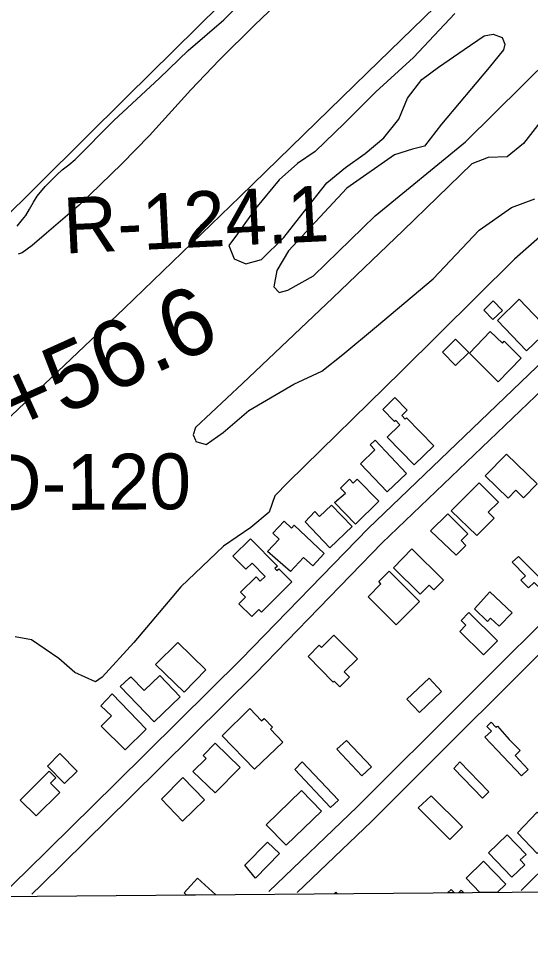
# Model space of a CAD drawing. Extents: x 3568792 to 3606828, y 529143 to 554785.
# Drawn here: x 3579710 to 3580470, y 534531 to 535909 of the extents above; entities that cross this region are included whole.
import ezdxf

# ---------------------------------------------------------------- set-up
doc = ezdxf.new("R2010")
doc.units = 0
for name, color, linetype in [('V-BLDG-OTLN', 7, 'Continuous'), ('V-DTCH-CNTR', 7, 'Continuous'), ('V-GRID-FRAM', 7, 'Continuous'), ('V-RIVR-RANG-IDEN', 7, 'Continuous'), ('V-ROAD-CNTR', 7, 'Continuous'), ('V-SITE-VEGE', 7, 'Continuous'), ('V-SURV-IDEN', 7, 'Continuous')]:
    doc.layers.add(name, color=color, linetype=linetype)

msp = doc.modelspace()

# ---------------------------------------------------------------- linework, layer by layer
at = {"layer": 'V-BLDG-OTLN'}
for p, q in [((3580374.8, 534631.4), (3580400.8, 534656.7)), ((3580400.8, 534656.7), (3580433.9, 534622.4)), ((3579955.9, 534609.4), (3579975.7, 534631.5)), ((3579975.7, 534631.5), (3580003, 534606.6)), ((3580395.5, 534609.9), (3580374.8, 534631.4)), ((3579959.4, 534606.2), (3579955.9, 534609.4)), ((3580178.9, 534608.1), (3580181.4, 534610.6)), ((3580181.4, 534610.6), (3580183.9, 534608.1)), ((3580347.4, 534609.5), (3580352.9, 534614.5)), ((3580357.8, 534609.6), (3580347.4, 534609.5)), ((3580352.9, 534614.5), (3580357.8, 534609.6)), ((3580363.6, 534609.6), (3580367.5, 534613.5)), ((3580371.3, 534609.7), (3580363.6, 534609.6)), ((3580367.5, 534613.5), (3580371.3, 534609.7)), ((3580421.2, 534610.1), (3580395.5, 534609.9)), ((3580433.9, 534622.4), (3580421.2, 534610.1)), ((3580003, 534606.6), (3579959.4, 534606.2)), ((3580183.9, 534608.1), (3580178.9, 534608.1))]:
    msp.add_line(p, q, dxfattribs=at)
for points in [[(3580421.6, 535460.7), (3580453.9, 535492.1), (3580497.3, 535446.5), (3580464.7, 535415.5)], [(3580401.2, 535476), (3580415.2, 535489.6), (3580428.8, 535475.4), (3580414.7, 535461.9)], [(3580379.7, 535411.8), (3580410.6, 535444.2), (3580429, 535426.9), (3580431.3, 535429.7), (3580456.7, 535404.5), (3580422.7, 535369.5)], [(3580339.6, 535413.5), (3580359.3, 535432.7), (3580378.7, 535412.7), (3580358.9, 535393.5)], [(3580257.7, 535286.8), (3580276.6, 535305.6), (3580270.3, 535311.9), (3580268.6, 535310.2), (3580251, 535328.1), (3580269.2, 535345.9), (3580287.4, 535327.3), (3580279.2, 535319.3), (3580284.4, 535314), (3580286.1, 535315.6), (3580326.7, 535274.2), (3580297.8, 535245.9)], [(3580217.9, 535247.4), (3580239.4, 535268.4), (3580232.5, 535275.7), (3580239.8, 535282.6), (3580286.5, 535233.2), (3580257.5, 535205.7)], [(3580403.4, 535229.4), (3580434.8, 535261.6), (3580480.4, 535217.4), (3580460.3, 535196.7), (3580448.6, 535208), (3580437.4, 535196.4)], [(3580179.4, 535190), (3580195.5, 535204), (3580188.2, 535211.4), (3580201.5, 535224.4), (3580207.1, 535218.7), (3580213.1, 535224.7), (3580245.3, 535191.7), (3580210.7, 535157.9)], [(3580352.8, 535177.5), (3580394.3, 535219.2), (3580423.1, 535190.5), (3580407.9, 535175.3), (3580416.6, 535166.6), (3580390.7, 535140.6)], [(3580135.7, 535161.1), (3580150, 535176.3), (3580156.9, 535169), (3580174.8, 535186.1), (3580205.5, 535154.1), (3580172.6, 535122.6)], [(3580079.9, 535117), (3580097.1, 535135.4), (3580087.7, 535144.2), (3580104.3, 535162), (3580115.3, 535151.7), (3580119.4, 535156.1), (3580164.2, 535114), (3580146.9, 535095.6), (3580133.3, 535108.3), (3580113.7, 535087.4)], [(3580321.8, 535147.7), (3580347.5, 535173.2), (3580377.3, 535143.2), (3580367.3, 535133.3), (3580374.7, 535125.9), (3580360.2, 535111.6)], [(3580028.3, 535110.1), (3580054.4, 535135.8), (3580094.5, 535095.2), (3580090.9, 535091.7), (3580093.7, 535088.8), (3580096.5, 535091.5), (3580116, 535071.7), (3580070.7, 535027), (3580066.9, 535030.9), (3580056.3, 535020.4), (3580037.4, 535039.4), (3580047.2, 535049.1), (3580039.9, 535056.5), (3580062.8, 535079.2), (3580069.1, 535072.9), (3580076.4, 535080), (3580057, 535099.8), (3580047.8, 535090.7)], [(3580267, 535092.7), (3580294, 535121), (3580341.1, 535074.3), (3580327, 535060.1), (3580319.8, 535067.2), (3580306.4, 535053.6)], [(3580452.6, 535109.5), (3580495.2, 535067.1), (3580487.7, 535059.5), (3580476.1, 535071.1), (3580467.7, 535062.8), (3580456.3, 535074.2), (3580463.1, 535081), (3580443.1, 535101)], [(3580229.3, 535049.8), (3580248.3, 535069.1), (3580245, 535072.4), (3580260.4, 535087.9), (3580305.4, 535042.8), (3580270.8, 535008.2)], [(3580410.2, 535057.2), (3580443.2, 535025.8), (3580424.1, 535005.8), (3580411.3, 535018), (3580406.6, 535013.1), (3580387.2, 535031.6)], [(3580378.7, 535026.3), (3580421.3, 534984.3), (3580400.7, 534963.4), (3580365.4, 534998.2), (3580374.6, 535007.4), (3580367.6, 535014.3)], [(3579913.5, 534948.9), (3579946.3, 534981.6), (3579988.2, 534941.2), (3579956.1, 534907.8)], [(3580140, 534960.8), (3580156.6, 534977.7), (3580159.9, 534974.4), (3580178.4, 534992.8), (3580213.3, 534957.4), (3580193.8, 534938), (3580201.6, 534930.1), (3580187.1, 534915.7), (3580178.7, 534924.2), (3580177.5, 534923)], [(3579860.9, 534916.2), (3579874.4, 534928.9), (3579876.5, 534930.9), (3579896.4, 534910.3), (3579919.6, 534932.7), (3579950.2, 534900.9), (3579911.5, 534863.6)], [(3580286.9, 534897.5), (3580319.8, 534928.6), (3580338.3, 534909), (3580305.4, 534877.9)], [(3579832.6, 534857.2), (3579848, 534872.7), (3579832.1, 534887.5), (3579848.9, 534905.2), (3579899.7, 534852.7), (3579868.2, 534822.3)], [(3580012.5, 534843.2), (3580053.5, 534883.4), (3580071.1, 534865.2), (3580074.7, 534868.8), (3580087.3, 534855.7), (3580084.4, 534852.9), (3580102.7, 534833.8), (3580060.6, 534793.3)], [(3580402.7, 534840.9), (3580412.5, 534850), (3580405.8, 534856.7), (3580411.9, 534863.4), (3580418.9, 534855.7), (3580421.3, 534857.3), (3580438.9, 534837.5), (3580455.3, 534821), (3580447.6, 534813.5), (3580466.9, 534793.1), (3580457, 534783.7)], [(3579969, 534790.2), (3579988.4, 534809.5), (3579984.2, 534813.6), (3580002, 534831.9), (3580039, 534795.9), (3580002.1, 534758)], [(3580182.6, 534823.2), (3580197.3, 534836.1), (3580234.1, 534796.7), (3580219.8, 534783.3)], [(3579752.7, 534797.8), (3579771, 534816.7), (3579796.9, 534790.5), (3579778.2, 534772)], [(3580120.5, 534792.8), (3580131.3, 534804.3), (3580185.1, 534747.3), (3580173.6, 534736.5)], [(3580356.5, 534794.5), (3580365.8, 534804.1), (3580408.8, 534759.5), (3580399.2, 534750.2)], [(3579712.1, 534747.5), (3579755.5, 534790.4), (3579765.3, 534780.5), (3579757.2, 534772.5), (3579771, 534758.6), (3579735.9, 534723.9)], [(3579922.2, 534748.7), (3579954.2, 534781), (3579986.1, 534747.9), (3579953.4, 534716.3)], [(3580077.6, 534710.5), (3580130.4, 534761.6), (3580159.9, 534731.1), (3580107.6, 534680.4)], [(3580303.6, 534735.9), (3580323, 534753.9), (3580369.3, 534707.7), (3580350.6, 534689)], [(3580451.1, 534699), (3580480.6, 534729.7), (3580503.9, 534707.2), (3580489.7, 534692.4), (3580497.2, 534685.2), (3580480.5, 534668)], [(3580408.3, 534669.2), (3580436.1, 534696), (3580464, 534666.8), (3580455.4, 534658.6), (3580462.3, 534651.4), (3580442.8, 534632.9)], [(3580046.1, 534650.6), (3580079.8, 534685.1), (3580097.4, 534668), (3580061.9, 534631.6)]]:
    msp.add_lwpolyline(points, close=True, dxfattribs=at)
at = {"layer": 'V-DTCH-CNTR'}
msp.add_lwpolyline([(3579345.4, 535955.3), (3579344.6, 535829.1), (3579355.7, 535629.1), (3579363.4, 535439), (3579368.5, 535307.8), (3579612.7, 535537.5), (3579870.9, 535793.2), (3580114.2, 536033.9)], dxfattribs=at)
at = {"layer": 'V-GRID-FRAM'}
msp.add_lwpolyline([(3570936, 552713.8), (3602582.8, 552980.8), (3602744.1, 534798.4), (3571081.5, 534531.3), (3570936, 552713.8)], dxfattribs=at)
at = {"layer": 'V-ROAD-CNTR'}
for points in [[(3579687.9, 534608.9), (3579722.4, 534642.3), (3579854.1, 534771.9), (3580040.5, 534957), (3580229.2, 535151.4), (3580479.9, 535391.4), (3580734.3, 535642.1), (3580870.3, 535779.1)], [(3579729.7, 534607.6), (3579743.3, 534620.8), (3579875.2, 534750.6), (3580061.9, 534935.9), (3580250.3, 535130.1), (3580500.8, 535369.9), (3580755.4, 535620.8), (3580891.6, 535758)], [(3580081.9, 534611.5), (3580213.1, 534737.3), (3580535.1, 535058.5), (3580814.5, 535338.4)], [(3580123.9, 534610.2), (3580234.1, 534715.8), (3580556.3, 535037.3), (3580835.7, 535317.2)], [(3580456.6, 534612.8), (3580504.7, 534660.4), (3580655.5, 534807.1), (3580819.6, 534963.7)]]:
    msp.add_lwpolyline(points, dxfattribs=at)
at = {"layer": 'V-SITE-VEGE'}
for points in [[(3579679.2, 535300.6), (3579866.8, 535478.4), (3580039.2, 535644.8), (3580228.1, 535828.9), (3580413.2, 536009.3)], [(3579707.6, 535600.8), (3579715.9, 535610.7), (3579720.5, 535616.4), (3579726.2, 535625.8), (3579732.3, 535636.6), (3579737.4, 535645.4), (3579749.3, 535659.5), (3579766.8, 535677), (3579774.5, 535684.6), (3579784.4, 535692.1), (3579794, 535699.7), (3579851.5, 535757.8), (3579919.3, 535820.8), (3579961.7, 535861.7), (3580014.7, 535907.6), (3580104.5, 535999.1)], [(3580121.7, 535958.6), (3580061.1, 535900.2), (3580008.6, 535847.9), (3579966, 535803.2), (3579904.2, 535735.7), (3579863.1, 535693.3), (3579799.9, 535632.1), (3579751.6, 535590.5), (3579729.9, 535571.9), (3579722.5, 535566.3), (3579715.3, 535561.2), (3579709.2, 535559.1)], [(3580357.9, 535916.9), (3580296.9, 535851.3), (3580240.9, 535800.3), (3580194.4, 535753.8), (3580150.6, 535711.7), (3580124.5, 535693.9), (3580097.1, 535669.7), (3580062.1, 535627), (3580035.4, 535589.4), (3580022.1, 535572.2), (3580030.4, 535552.4), (3580047.6, 535544.8), (3580071.1, 535551.2), (3580104.2, 535583.7), (3580132.8, 535620.7), (3580167.8, 535665.3), (3580195.8, 535688.2), (3580225, 535708.6), (3580252.4, 535732.2), (3580274.7, 535759.6), (3580288, 535790.8), (3580309, 535818.8), (3580333.8, 535837.3), (3580372, 535863.5), (3580401.9, 535883.9), (3580415.2, 535886.4), (3580428.6, 535881.3), (3580432.4, 535871.1), (3580430.5, 535862.9), (3580408.9, 535836.7), (3580338.3, 535752.6), (3580312.9, 535719.5), (3580295.1, 535715), (3580268.3, 535706.7), (3580197.7, 535657), (3580111.2, 535564), (3580093.4, 535534.7), (3580089, 535510.5), (3580097.3, 535502.2), (3580110, 535505.4), (3580148.2, 535527.1), (3580239.8, 535616.3), (3580374, 535725.9), (3580501.9, 535852.7)], [(3580541.4, 535828), (3580460, 535723.5), (3580435.8, 535703.7), (3580407.8, 535703), (3580383.6, 535693.5), (3580281.2, 535594.1), (3580176.9, 535494), (3580042.6, 535366.6), (3579972.7, 535301.5), (3579969.5, 535290.7), (3579972.7, 535282.4), (3579973.3, 535280.5), (3579988.6, 535276.1), (3580014.1, 535293.9), (3580052.2, 535326.5), (3580119, 535366), (3580160.4, 535385.1), (3580191.6, 535410), (3580241.8, 535451.4), (3580325.8, 535522.2), (3580394.5, 535594.8), (3580442.2, 535628.6), (3580477.2, 535641.4)], [(3580542.8, 535636.3), (3580446.8, 535551.6), (3580278.2, 535384.6), (3580110.3, 535220.2), (3580090.5, 535199.8), (3580082.3, 535175.6), (3580054.9, 535152.6), (3580014.2, 535125.2), (3579951.2, 535064.7), (3579881.3, 534981.9), (3579834.2, 534930.2), (3579824, 534923.2), (3579793.5, 534937.2), (3579769.9, 534958.2), (3579729.1, 534985.5), (3579704.9, 534990)]]:
    msp.add_lwpolyline(points, dxfattribs=at)

# ---------------------------------------------------------------- texts
at = {"layer": 'V-RIVR-RANG-IDEN'}
for s, rotation, p in [('R-124.1', 2.7369, (3579778.3, 535559.9)), ('D-120', 0.3293, (3579664.1, 535178.2))]:
    msp.add_text(s, height=83, rotation=rotation, dxfattribs=at).set_placement(p)
at = {"layer": 'V-SURV-IDEN'}
msp.add_text('5450+56.6', height=100, rotation=24.3201, dxfattribs=at).set_placement((3579433.7, 535164.7))

doc.saveas('drawing.dxf')
